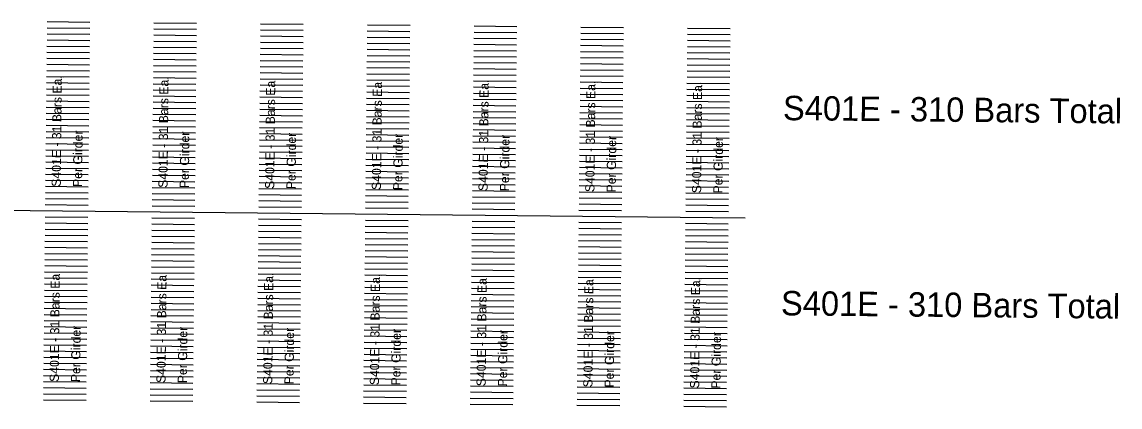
# Model space of a CAD drawing. Extents: x 632547 to 633311, y 380830 to 386139.
# Drawn here: x 633157.1 to 633247.1, y 381273.9 to 381305.5 of the extents above; entities that cross this region are included whole.
import ezdxf

# ---------------------------------------------------------------- set-up
doc = ezdxf.new("R2010")
doc.units = 0
for name, color, linetype in [('B_Border', 7, 'Continuous'), ('R_Border_Scale', 7, 'Continuous'), ('R_Wall', 7, 'Continuous')]:
    doc.layers.add(name, color=color, linetype=linetype)

msp = doc.modelspace()

# ---------------------------------------------------------------- linework, layer by layer
at = {"layer": 'B_Border'}
msp.add_line((633216.37, 381289.395), (633099.316, 381290.579), dxfattribs=at)
at = {"layer": 'R_Border_Scale'}
for p, q in [((633162.65, 381304.939), (633159.15, 381304.975)), ((633162.655, 381305.439), (633159.155, 381305.475)), ((633171.399, 381304.851), (633167.899, 381304.886)), ((633171.404, 381305.351), (633167.904, 381305.386)), ((633180.149, 381304.762), (633176.649, 381304.798)), ((633180.154, 381305.262), (633176.654, 381305.298)), ((633188.898, 381304.674), (633185.398, 381304.709)), ((633188.903, 381305.174), (633185.403, 381305.209)), ((633197.653, 381305.085), (633194.153, 381305.121)), ((633206.402, 381304.997), (633202.903, 381305.032)), ((633215.152, 381304.908), (633211.652, 381304.944)), ((633162.639, 381303.939), (633159.14, 381303.975)), ((633162.644, 381304.439), (633159.145, 381304.475)), ((633171.389, 381303.851), (633167.889, 381303.886)), ((633171.394, 381304.351), (633167.894, 381304.386)), ((633180.144, 381304.262), (633176.644, 381304.298)), ((633188.893, 381304.174), (633185.393, 381304.209)), ((633197.643, 381304.085), (633194.143, 381304.121)), ((633197.648, 381304.585), (633194.148, 381304.621)), ((633206.392, 381303.997), (633202.892, 381304.032)), ((633206.397, 381304.497), (633202.897, 381304.532)), ((633215.142, 381303.908), (633211.642, 381303.944)), ((633215.147, 381304.408), (633211.647, 381304.444)), ((633162.629, 381302.94), (633159.129, 381302.975)), ((633162.634, 381303.44), (633159.135, 381303.475)), ((633171.384, 381303.351), (633167.884, 381303.386)), ((633180.133, 381303.262), (633176.634, 381303.298)), ((633180.139, 381303.762), (633176.639, 381303.798)), ((633188.883, 381303.174), (633185.383, 381303.209)), ((633188.888, 381303.674), (633185.388, 381303.709)), ((633197.633, 381303.085), (633194.133, 381303.121)), ((633197.638, 381303.585), (633194.138, 381303.621)), ((633206.382, 381302.997), (633202.882, 381303.032)), ((633206.387, 381303.497), (633202.887, 381303.532)), ((633215.132, 381302.908), (633211.632, 381302.944)), ((633215.137, 381303.408), (633211.637, 381303.444)), ((633162.624, 381302.44), (633159.124, 381302.475)), ((633171.374, 381302.351), (633167.874, 381302.386)), ((633171.379, 381302.851), (633167.879, 381302.886)), ((633180.123, 381302.263), (633176.624, 381302.298)), ((633180.128, 381302.763), (633176.629, 381302.798)), ((633188.873, 381302.174), (633185.373, 381302.209)), ((633188.878, 381302.674), (633185.378, 381302.709)), ((633197.622, 381302.085), (633194.123, 381302.121)), ((633197.628, 381302.585), (633194.128, 381302.621)), ((633206.372, 381301.997), (633202.872, 381302.032)), ((633206.377, 381302.497), (633202.877, 381302.532)), ((633215.127, 381302.408), (633211.627, 381302.444)), ((633162.614, 381301.44), (633159.114, 381301.475)), ((633162.619, 381301.94), (633159.119, 381301.975)), ((633171.364, 381301.351), (633167.864, 381301.387)), ((633171.369, 381301.851), (633167.869, 381301.886)), ((633180.113, 381301.263), (633176.613, 381301.298)), ((633180.118, 381301.763), (633176.618, 381301.798)), ((633188.863, 381301.174), (633185.363, 381301.209)), ((633188.868, 381301.674), (633185.368, 381301.709)), ((633197.612, 381301.086), (633194.113, 381301.121)), ((633197.617, 381301.586), (633194.118, 381301.621)), ((633206.367, 381301.497), (633202.867, 381301.532)), ((633215.116, 381301.408), (633211.617, 381301.444)), ((633215.122, 381301.908), (633211.622, 381301.944)), ((633162.604, 381300.44), (633159.104, 381300.475)), ((633162.609, 381300.94), (633159.109, 381300.975)), ((633171.354, 381300.351), (633167.854, 381300.387)), ((633171.359, 381300.851), (633167.859, 381300.887)), ((633180.103, 381300.263), (633176.603, 381300.298)), ((633180.108, 381300.763), (633176.608, 381300.798)), ((633188.853, 381300.174), (633185.353, 381300.21)), ((633188.858, 381300.674), (633185.358, 381300.709)), ((633197.607, 381300.586), (633194.107, 381300.621)), ((633206.357, 381300.497), (633202.857, 381300.532)), ((633206.362, 381300.997), (633202.862, 381301.032)), ((633215.106, 381300.409), (633211.607, 381300.444)), ((633215.111, 381300.909), (633211.612, 381300.944)), ((633162.594, 381299.44), (633159.094, 381299.475)), ((633162.599, 381299.94), (633159.099, 381299.975)), ((633171.343, 381299.351), (633167.844, 381299.387)), ((633171.349, 381299.851), (633167.849, 381299.887)), ((633180.098, 381299.763), (633176.598, 381299.798)), ((633188.848, 381299.674), (633185.348, 381299.71)), ((633197.597, 381299.586), (633194.097, 381299.621)), ((633197.602, 381300.086), (633194.102, 381300.121)), ((633206.347, 381299.497), (633202.847, 381299.533)), ((633206.352, 381299.997), (633202.852, 381300.032)), ((633215.096, 381299.409), (633211.596, 381299.444)), ((633215.101, 381299.909), (633211.601, 381299.944)), ((633162.584, 381298.44), (633159.084, 381298.475)), ((633162.589, 381298.94), (633159.089, 381298.975)), ((633171.338, 381298.851), (633167.839, 381298.887)), ((633180.088, 381298.763), (633176.588, 381298.798)), ((633180.093, 381299.263), (633176.593, 381299.298)), ((633188.837, 381298.674), (633185.338, 381298.71)), ((633188.843, 381299.174), (633185.343, 381299.21)), ((633197.587, 381298.586), (633194.087, 381298.621)), ((633197.592, 381299.086), (633194.092, 381299.121)), ((633206.337, 381298.497), (633202.837, 381298.533)), ((633206.342, 381298.997), (633202.842, 381299.033)), ((633215.086, 381298.409), (633211.586, 381298.444)), ((633215.091, 381298.909), (633211.591, 381298.944)), ((633162.579, 381297.94), (633159.079, 381297.975)), ((633171.328, 381297.851), (633167.828, 381297.887)), ((633171.333, 381298.351), (633167.834, 381298.387)), ((633180.078, 381297.763), (633176.578, 381297.798)), ((633180.083, 381298.263), (633176.583, 381298.298)), ((633188.827, 381297.674), (633185.328, 381297.71)), ((633188.832, 381298.174), (633185.333, 381298.21)), ((633197.577, 381297.586), (633194.077, 381297.621)), ((633197.582, 381298.086), (633194.082, 381298.121)), ((633206.326, 381297.497), (633202.827, 381297.533)), ((633206.332, 381297.997), (633202.832, 381298.033)), ((633215.081, 381297.909), (633211.581, 381297.944)), ((633162.569, 381296.94), (633159.069, 381296.975)), ((633162.574, 381297.44), (633159.074, 381297.475)), ((633171.318, 381296.851), (633167.818, 381296.887)), ((633171.323, 381297.351), (633167.823, 381297.387)), ((633180.068, 381296.763), (633176.568, 381296.798)), ((633180.073, 381297.263), (633176.573, 381297.298)), ((633188.817, 381296.674), (633185.317, 381296.71)), ((633188.822, 381297.174), (633185.322, 381297.21)), ((633197.567, 381296.586), (633194.067, 381296.621)), ((633197.572, 381297.086), (633194.072, 381297.121)), ((633206.321, 381296.997), (633202.822, 381297.033)), ((633215.071, 381296.909), (633211.571, 381296.944)), ((633215.076, 381297.409), (633211.576, 381297.444)), ((633162.558, 381295.94), (633159.059, 381295.975)), ((633162.564, 381296.44), (633159.064, 381296.475)), ((633171.308, 381295.851), (633167.808, 381295.887)), ((633171.313, 381296.351), (633167.813, 381296.387)), ((633180.058, 381295.763), (633176.558, 381295.798)), ((633180.063, 381296.263), (633176.563, 381296.298)), ((633188.807, 381295.674), (633185.307, 381295.71)), ((633188.812, 381296.174), (633185.312, 381296.21)), ((633197.562, 381296.086), (633194.062, 381296.121)), ((633206.311, 381295.997), (633202.811, 381296.033)), ((633206.316, 381296.497), (633202.817, 381296.533)), ((633215.061, 381295.909), (633211.561, 381295.944)), ((633215.066, 381296.409), (633211.566, 381296.444)), ((633162.548, 381294.94), (633159.049, 381294.975)), ((633162.553, 381295.44), (633159.054, 381295.475)), ((633171.298, 381294.851), (633167.798, 381294.887)), ((633171.303, 381295.351), (633167.803, 381295.387)), ((633180.053, 381295.263), (633176.553, 381295.298)), ((633188.802, 381295.174), (633185.302, 381295.21)), ((633197.552, 381295.086), (633194.052, 381295.121)), ((633197.557, 381295.586), (633194.057, 381295.621)), ((633206.301, 381294.997), (633202.801, 381295.033)), ((633206.306, 381295.497), (633202.806, 381295.533)), ((633215.051, 381294.909), (633211.551, 381294.944)), ((633215.056, 381295.409), (633211.556, 381295.444)), ((633162.538, 381293.94), (633159.038, 381293.975)), ((633162.543, 381294.44), (633159.043, 381294.475)), ((633171.293, 381294.351), (633167.793, 381294.387)), ((633180.042, 381294.263), (633176.543, 381294.298)), ((633180.047, 381294.763), (633176.548, 381294.798)), ((633188.792, 381294.174), (633185.292, 381294.21)), ((633188.797, 381294.674), (633185.297, 381294.71)), ((633197.542, 381294.086), (633194.042, 381294.121)), ((633197.547, 381294.586), (633194.047, 381294.621)), ((633206.291, 381293.997), (633202.791, 381294.033)), ((633206.296, 381294.497), (633202.796, 381294.533)), ((633215.041, 381293.909), (633211.541, 381293.944)), ((633215.046, 381294.409), (633211.546, 381294.444)), ((633162.533, 381293.44), (633159.033, 381293.475)), ((633171.283, 381293.352), (633167.783, 381293.387)), ((633171.288, 381293.851), (633167.788, 381293.887)), ((633180.032, 381293.263), (633176.532, 381293.298)), ((633180.037, 381293.763), (633176.538, 381293.798)), ((633188.782, 381293.174), (633185.282, 381293.21)), ((633188.787, 381293.674), (633185.287, 381293.71)), ((633197.531, 381293.086), (633194.032, 381293.121)), ((633197.536, 381293.586), (633194.037, 381293.621)), ((633206.281, 381292.997), (633202.781, 381293.033)), ((633206.286, 381293.497), (633202.786, 381293.533)), ((633215.036, 381293.409), (633211.536, 381293.444)), ((633162.523, 381292.44), (633159.023, 381292.475)), ((633162.528, 381292.94), (633159.028, 381292.975)), ((633171.273, 381292.352), (633167.773, 381292.387)), ((633171.278, 381292.852), (633167.778, 381292.887)), ((633180.022, 381292.263), (633176.522, 381292.298)), ((633180.027, 381292.763), (633176.527, 381292.798)), ((633188.772, 381292.175), (633185.272, 381292.21)), ((633188.777, 381292.674), (633185.277, 381292.71)), ((633197.521, 381292.086), (633194.021, 381292.121)), ((633197.526, 381292.586), (633194.027, 381292.621)), ((633206.276, 381292.497), (633202.776, 381292.533)), ((633215.025, 381292.409), (633211.526, 381292.444)), ((633215.031, 381292.909), (633211.531, 381292.944)), ((633162.513, 381291.44), (633159.013, 381291.476)), ((633162.518, 381291.94), (633159.018, 381291.976)), ((633171.263, 381291.352), (633167.763, 381291.387)), ((633171.268, 381291.852), (633167.768, 381291.887)), ((633180.012, 381291.263), (633176.512, 381291.299)), ((633180.017, 381291.763), (633176.517, 381291.798)), ((633188.762, 381291.175), (633185.262, 381291.21)), ((633188.767, 381291.675), (633185.267, 381291.71)), ((633197.516, 381291.586), (633194.016, 381291.621)), ((633206.266, 381291.498), (633202.766, 381291.533)), ((633206.271, 381291.997), (633202.771, 381292.033)), ((633215.015, 381291.409), (633211.516, 381291.444)), ((633215.02, 381291.909), (633211.521, 381291.944)), ((633162.503, 381290.44), (633159.003, 381290.476)), ((633162.508, 381290.94), (633159.008, 381290.976)), ((633171.252, 381290.352), (633167.753, 381290.387)), ((633171.257, 381290.852), (633167.758, 381290.887)), ((633180.007, 381290.763), (633176.507, 381290.799)), ((633188.757, 381290.675), (633185.257, 381290.71)), ((633197.506, 381290.586), (633194.006, 381290.621)), ((633197.511, 381291.086), (633194.011, 381291.121)), ((633206.256, 381290.498), (633202.756, 381290.533)), ((633206.261, 381290.998), (633202.761, 381291.033)), ((633215.005, 381290.409), (633211.505, 381290.444)), ((633215.01, 381290.909), (633211.51, 381290.944)), ((633162.493, 381289.44), (633158.993, 381289.476)), ((633180.002, 381290.263), (633176.502, 381290.299)), ((633188.751, 381290.175), (633185.252, 381290.21)), ((633197.501, 381290.086), (633194.001, 381290.122)), ((633206.251, 381289.998), (633202.751, 381290.033)), ((633215, 381289.909), (633211.5, 381289.944)), ((633162.488, 381288.94), (633158.988, 381288.976)), ((633171.237, 381288.852), (633167.737, 381288.887)), ((633171.242, 381289.352), (633167.742, 381289.387)), ((633179.987, 381288.763), (633176.487, 381288.799)), ((633179.992, 381289.263), (633176.492, 381289.299)), ((633188.736, 381288.675), (633185.237, 381288.71)), ((633188.741, 381289.175), (633185.242, 381289.21)), ((633197.486, 381288.586), (633193.986, 381288.622)), ((633197.491, 381289.086), (633193.991, 381289.122)), ((633206.235, 381288.498), (633202.736, 381288.533)), ((633206.24, 381288.998), (633202.741, 381289.033)), ((633214.99, 381288.909), (633211.49, 381288.945)), ((633162.478, 381287.94), (633158.978, 381287.976)), ((633162.483, 381288.44), (633158.983, 381288.476)), ((633171.227, 381287.852), (633167.727, 381287.887)), ((633171.232, 381288.352), (633167.732, 381288.387)), ((633179.977, 381287.763), (633176.477, 381287.799)), ((633179.982, 381288.263), (633176.482, 381288.299)), ((633188.726, 381287.675), (633185.226, 381287.71)), ((633188.731, 381288.175), (633185.231, 381288.21)), ((633197.476, 381287.586), (633193.976, 381287.622)), ((633197.481, 381288.086), (633193.981, 381288.122)), ((633206.23, 381287.998), (633202.731, 381288.033)), ((633214.98, 381287.909), (633211.48, 381287.945)), ((633214.985, 381288.409), (633211.485, 381288.445)), ((633162.467, 381286.94), (633158.968, 381286.976)), ((633162.472, 381287.44), (633158.973, 381287.476)), ((633171.217, 381286.852), (633167.717, 381286.887)), ((633171.222, 381287.352), (633167.722, 381287.387)), ((633179.967, 381286.763), (633176.467, 381286.799)), ((633179.972, 381287.263), (633176.472, 381287.299)), ((633188.716, 381286.675), (633185.216, 381286.71)), ((633188.721, 381287.175), (633185.221, 381287.21)), ((633197.471, 381287.086), (633193.971, 381287.122)), ((633206.22, 381286.998), (633202.72, 381287.033)), ((633206.225, 381287.498), (633202.725, 381287.533)), ((633214.97, 381286.909), (633211.47, 381286.945)), ((633214.975, 381287.409), (633211.475, 381287.445)), ((633162.457, 381285.94), (633158.957, 381285.976)), ((633162.462, 381286.44), (633158.963, 381286.476)), ((633171.207, 381285.852), (633167.707, 381285.887)), ((633171.212, 381286.352), (633167.712, 381286.387)), ((633179.956, 381285.763), (633176.457, 381285.799)), ((633179.961, 381286.263), (633176.462, 381286.299)), ((633188.711, 381286.175), (633185.211, 381286.21)), ((633197.461, 381286.086), (633193.961, 381286.122)), ((633197.466, 381286.586), (633193.966, 381286.622)), ((633206.21, 381285.998), (633202.71, 381286.033)), ((633206.215, 381286.498), (633202.715, 381286.533)), ((633214.96, 381285.909), (633211.46, 381285.945)), ((633214.965, 381286.409), (633211.465, 381286.445)), ((633162.447, 381284.94), (633158.947, 381284.976)), ((633162.452, 381285.44), (633158.952, 381285.476)), ((633171.202, 381285.352), (633167.702, 381285.387)), ((633179.951, 381285.263), (633176.452, 381285.299)), ((633188.701, 381285.175), (633185.201, 381285.21)), ((633188.706, 381285.675), (633185.206, 381285.71)), ((633197.45, 381285.086), (633193.951, 381285.122)), ((633197.456, 381285.586), (633193.956, 381285.622)), ((633206.2, 381284.998), (633202.7, 381285.033)), ((633206.205, 381285.498), (633202.705, 381285.533)), ((633214.95, 381284.909), (633211.45, 381284.945)), ((633214.955, 381285.409), (633211.455, 381285.445)), ((633162.442, 381284.44), (633158.942, 381284.476)), ((633171.192, 381284.352), (633167.692, 381284.387)), ((633171.197, 381284.852), (633167.697, 381284.887)), ((633179.941, 381284.263), (633176.441, 381284.299)), ((633179.946, 381284.763), (633176.446, 381284.799)), ((633188.691, 381284.175), (633185.191, 381284.21)), ((633188.696, 381284.675), (633185.196, 381284.71)), ((633197.44, 381284.086), (633193.941, 381284.122)), ((633197.445, 381284.586), (633193.946, 381284.622)), ((633206.19, 381283.998), (633202.69, 381284.033)), ((633206.195, 381284.498), (633202.695, 381284.533)), ((633214.945, 381284.409), (633211.445, 381284.445)), ((633162.432, 381283.441), (633158.932, 381283.476)), ((633162.437, 381283.941), (633158.937, 381283.976)), ((633171.182, 381283.352), (633167.682, 381283.387)), ((633171.187, 381283.852), (633167.687, 381283.887)), ((633179.931, 381283.264), (633176.431, 381283.299)), ((633179.936, 381283.763), (633176.436, 381283.799)), ((633188.681, 381283.175), (633185.181, 381283.21)), ((633188.686, 381283.675), (633185.186, 381283.71)), ((633197.43, 381283.086), (633193.93, 381283.122)), ((633197.435, 381283.586), (633193.935, 381283.622)), ((633206.185, 381283.498), (633202.685, 381283.533)), ((633214.934, 381283.409), (633211.435, 381283.445)), ((633214.939, 381283.909), (633211.44, 381283.945)), ((633162.422, 381282.441), (633158.922, 381282.476)), ((633162.427, 381282.941), (633158.927, 381282.976)), ((633171.171, 381282.352), (633167.672, 381282.387)), ((633171.177, 381282.852), (633167.677, 381282.887)), ((633179.921, 381282.264), (633176.421, 381282.299)), ((633179.926, 381282.764), (633176.426, 381282.799)), ((633188.671, 381282.175), (633185.171, 381282.21)), ((633188.676, 381282.675), (633185.176, 381282.71)), ((633197.425, 381282.586), (633193.925, 381282.622)), ((633206.175, 381282.498), (633202.675, 381282.533)), ((633206.18, 381282.998), (633202.68, 381283.033)), ((633214.924, 381282.409), (633211.424, 381282.445)), ((633214.929, 381282.909), (633211.43, 381282.945)), ((633162.412, 381281.441), (633158.912, 381281.476)), ((633162.417, 381281.941), (633158.917, 381281.976)), ((633171.161, 381281.352), (633167.662, 381281.388)), ((633171.166, 381281.852), (633167.667, 381281.888)), ((633179.911, 381281.264), (633176.411, 381281.299)), ((633179.916, 381281.764), (633176.416, 381281.799)), ((633188.666, 381281.675), (633185.166, 381281.71)), ((633197.415, 381281.587), (633193.915, 381281.622)), ((633197.42, 381282.087), (633193.92, 381282.122)), ((633206.165, 381281.498), (633202.665, 381281.533)), ((633206.17, 381281.998), (633202.67, 381282.033)), ((633214.914, 381281.409), (633211.414, 381281.445)), ((633214.919, 381281.909), (633211.419, 381281.945)), ((633162.402, 381280.441), (633158.902, 381280.476)), ((633162.407, 381280.941), (633158.907, 381280.976)), ((633171.156, 381280.852), (633167.656, 381280.888)), ((633179.906, 381280.764), (633176.406, 381280.799)), ((633188.655, 381280.675), (633185.156, 381280.711)), ((633188.66, 381281.175), (633185.161, 381281.21)), ((633197.405, 381280.587), (633193.905, 381280.622)), ((633197.41, 381281.087), (633193.91, 381281.122)), ((633206.154, 381280.498), (633202.655, 381280.533)), ((633206.16, 381280.998), (633202.66, 381281.033)), ((633214.904, 381280.41), (633211.404, 381280.445)), ((633214.909, 381280.91), (633211.409, 381280.945)), ((633162.397, 381279.941), (633158.897, 381279.976)), ((633171.146, 381279.852), (633167.646, 381279.888)), ((633171.151, 381280.352), (633167.651, 381280.388)), ((633179.896, 381279.764), (633176.396, 381279.799)), ((633179.901, 381280.264), (633176.401, 381280.299)), ((633188.645, 381279.675), (633185.145, 381279.711)), ((633188.65, 381280.175), (633185.151, 381280.211)), ((633197.395, 381279.587), (633193.895, 381279.622)), ((633197.4, 381280.087), (633193.9, 381280.122)), ((633206.144, 381279.498), (633202.645, 381279.534)), ((633206.149, 381279.998), (633202.65, 381280.034)), ((633214.899, 381279.91), (633211.399, 381279.945)), ((633162.386, 381278.941), (633158.887, 381278.976)), ((633162.392, 381279.441), (633158.892, 381279.476)), ((633171.136, 381278.852), (633167.636, 381278.888)), ((633171.141, 381279.352), (633167.641, 381279.388)), ((633179.886, 381278.764), (633176.386, 381278.799)), ((633179.891, 381279.264), (633176.391, 381279.299)), ((633188.635, 381278.675), (633185.135, 381278.711)), ((633188.64, 381279.175), (633185.14, 381279.211)), ((633197.385, 381278.587), (633193.885, 381278.622)), ((633197.39, 381279.087), (633193.89, 381279.122)), ((633206.139, 381278.998), (633202.639, 381279.034)), ((633214.889, 381278.91), (633211.389, 381278.945)), ((633214.894, 381279.41), (633211.394, 381279.445)), ((633162.376, 381277.941), (633158.877, 381277.976)), ((633162.381, 381278.441), (633158.882, 381278.476)), ((633171.126, 381277.852), (633167.626, 381277.888)), ((633171.131, 381278.352), (633167.631, 381278.388)), ((633179.875, 381277.764), (633176.376, 381277.799)), ((633179.881, 381278.264), (633176.381, 381278.299)), ((633188.625, 381277.675), (633185.125, 381277.711)), ((633188.63, 381278.175), (633185.13, 381278.211)), ((633197.38, 381278.087), (633193.88, 381278.122)), ((633206.129, 381277.998), (633202.629, 381278.034)), ((633206.134, 381278.498), (633202.634, 381278.534)), ((633214.879, 381277.91), (633211.379, 381277.945)), ((633214.884, 381278.41), (633211.384, 381278.445)), ((633162.366, 381276.941), (633158.866, 381276.976)), ((633162.371, 381277.441), (633158.872, 381277.476)), ((633171.116, 381276.852), (633167.616, 381276.888)), ((633171.121, 381277.352), (633167.621, 381277.388)), ((633179.865, 381276.764), (633176.366, 381276.799)), ((633179.87, 381277.264), (633176.371, 381277.299)), ((633188.62, 381277.175), (633185.12, 381277.211)), ((633197.37, 381277.087), (633193.87, 381277.122)), ((633197.375, 381277.587), (633193.875, 381277.622)), ((633206.119, 381276.998), (633202.619, 381277.034)), ((633206.124, 381277.498), (633202.624, 381277.534)), ((633214.869, 381276.91), (633211.369, 381276.945)), ((633214.874, 381277.41), (633211.374, 381277.445)), ((633162.356, 381275.941), (633158.856, 381275.976)), ((633162.361, 381276.441), (633158.861, 381276.476)), ((633171.111, 381276.352), (633167.611, 381276.388)), ((633179.86, 381276.264), (633176.36, 381276.299)), ((633188.61, 381276.175), (633185.11, 381276.211)), ((633188.615, 381276.675), (633185.115, 381276.711)), ((633197.359, 381276.087), (633193.86, 381276.122)), ((633197.364, 381276.587), (633193.865, 381276.622)), ((633206.109, 381275.998), (633202.609, 381276.034)), ((633206.114, 381276.498), (633202.614, 381276.534)), ((633214.859, 381275.91), (633211.359, 381275.945)), ((633214.864, 381276.41), (633211.364, 381276.445)), ((633162.351, 381275.441), (633158.851, 381275.476)), ((633171.101, 381275.352), (633167.601, 381275.388)), ((633171.106, 381275.852), (633167.606, 381275.888)), ((633179.85, 381275.264), (633176.35, 381275.299)), ((633179.855, 381275.764), (633176.355, 381275.799)), ((633188.6, 381275.175), (633185.1, 381275.211)), ((633188.605, 381275.675), (633185.105, 381275.711)), ((633197.349, 381275.087), (633193.849, 381275.122)), ((633197.354, 381275.587), (633193.855, 381275.622)), ((633206.099, 381274.998), (633202.599, 381275.034)), ((633206.104, 381275.498), (633202.604, 381275.534)), ((633214.853, 381275.41), (633211.354, 381275.445)), ((633162.341, 381274.441), (633158.841, 381274.476)), ((633162.346, 381274.941), (633158.846, 381274.976)), ((633171.091, 381274.352), (633167.591, 381274.388)), ((633171.096, 381274.852), (633167.596, 381274.888)), ((633179.84, 381274.264), (633176.34, 381274.299)), ((633179.845, 381274.764), (633176.345, 381274.799)), ((633188.59, 381274.175), (633185.09, 381274.211)), ((633188.595, 381274.675), (633185.095, 381274.711)), ((633197.339, 381274.087), (633193.839, 381274.122)), ((633197.344, 381274.587), (633193.844, 381274.622)), ((633206.094, 381274.498), (633202.594, 381274.534)), ((633214.843, 381274.41), (633211.344, 381274.445)), ((633214.848, 381274.91), (633211.349, 381274.945)), ((633206.089, 381273.998), (633202.589, 381274.034)), ((633214.838, 381273.91), (633211.338, 381273.945))]:
    msp.add_line(p, q, dxfattribs=at)

# ---------------------------------------------------------------- texts
at = {"layer": 'R_Wall'}
for s, height, rotation, p in [('S401E - 31 Bars Ea,', 0.75, 89.43036, (633160.268, 381291.963)), ('S401E - 31 Bars Ea,', 0.75, 89.43036, (633169.018, 381291.874)), ('S401E - 31 Bars Ea,', 0.75, 89.43036, (633177.767, 381291.786)), ('S401E - 31 Bars Ea,', 0.75, 89.43036, (633186.517, 381291.697)), ('S401E - 31 Bars Ea,', 0.75, 89.43036, (633195.266, 381291.609)), ('S401E - 31 Bars Ea,', 0.75, 89.43036, (633204.016, 381291.52)), ('S401E - 31 Bars Ea,', 0.75, 89.43036, (633212.765, 381291.432)), ('S401E - 310 Bars Total', 2, 359.43036, (633219.47, 381297.428)), ('Per Girder', 0.75, 89.43036, (633162.018, 381291.945)), ('Per Girder', 0.75, 89.43036, (633170.768, 381291.857)), ('Per Girder', 0.75, 89.43036, (633179.517, 381291.768)), ('Per Girder', 0.75, 89.43036, (633188.267, 381291.68)), ('Per Girder', 0.75, 89.43036, (633197.016, 381291.591)), ('Per Girder', 0.75, 89.43036, (633205.766, 381291.503)), ('Per Girder', 0.75, 89.43036, (633214.515, 381291.414)), ('S401E - 31 Bars Ea,', 0.75, 89.43036, (633160.106, 381275.964)), ('S401E - 31 Bars Ea,', 0.75, 89.43036, (633168.856, 381275.875)), ('S401E - 31 Bars Ea,', 0.75, 89.43036, (633177.605, 381275.787)), ('S401E - 31 Bars Ea,', 0.75, 89.43036, (633186.355, 381275.698)), ('S401E - 31 Bars Ea,', 0.75, 89.43036, (633195.104, 381275.61)), ('S401E - 31 Bars Ea,', 0.75, 89.43036, (633203.854, 381275.521)), ('S401E - 31 Bars Ea,', 0.75, 89.43036, (633212.604, 381275.432)), ('S401E - 310 Bars Total', 2, 359.43036, (633219.308, 381281.429)), ('Per Girder', 0.75, 89.43036, (633161.856, 381275.946)), ('Per Girder', 0.75, 89.43036, (633170.606, 381275.858)), ('Per Girder', 0.75, 89.43036, (633179.355, 381275.769)), ('Per Girder', 0.75, 89.43036, (633188.105, 381275.681)), ('Per Girder', 0.75, 89.43036, (633196.854, 381275.592)), ('Per Girder', 0.75, 89.43036, (633205.604, 381275.504)), ('Per Girder', 0.75, 89.43036, (633214.353, 381275.415))]:
    msp.add_text(s, height=height, rotation=rotation, dxfattribs=at).set_placement(p)

doc.saveas('drawing.dxf')
